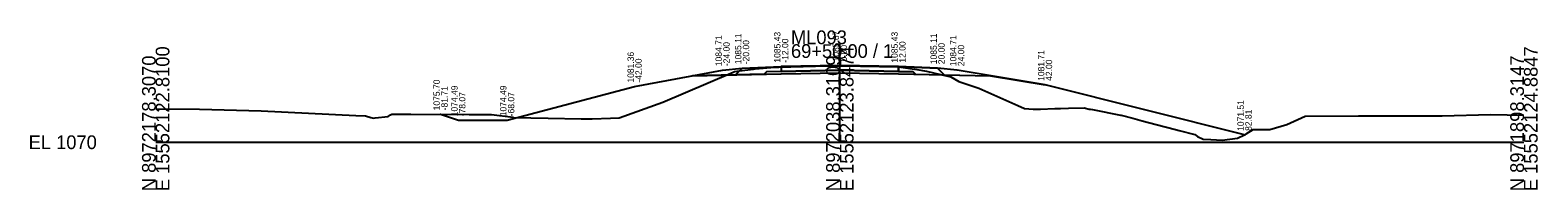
# Model space of a CAD drawing. Extents: x -26 to 14283, y -10 to 28.
# Drawn here: x 5974.3 to 6282.8, y -9.7 to 22.8 of the extents above; entities that cross this region are included whole.
import ezdxf

# ---------------------------------------------------------------- set-up
doc = ezdxf.new("R2010")
doc.units = 0
for name, color, linetype in [('Default', 7, 'Continuous'), ('dsn3DCenterLine', 7, 'Continuous'), ('dsn3DDitchBack', 7, 'Continuous'), ('dsn3DDitchFront', 7, 'Continuous'), ('dsn3DForeSlopeBarnRoofPoint', 7, 'Continuous'), ('dsn3DForeSlopeBreakLine', 7, 'Continuous'), ('dsn3DGroundLineIntercept', 7, 'Continuous'), ('dsn3DPavementTop', 7, 'Continuous'), ('dsn3DShoulderTop', 7, 'Continuous'), ('dsn3DSubgradeBreakLine', 7, 'Continuous'), ('dsn3DSubgradeHingePoint', 7, 'Continuous'), ('dsnGeopakCellCrossSection', 7, 'Continuous'), ('dsnXSEarthwork', 7, 'Continuous'), ('dsnXsExistingGround', 7, 'Continuous'), ('dsnXsPCCPavement', 7, 'Continuous'), ('dsnXsShldrEarthFill', 7, 'Continuous'), ('dsnXsShldrGranular', 7, 'Continuous'), ('dsnXsSideSlopes', 7, 'Continuous'), ('dsnXsSubbase', 7, 'Continuous'), ('dsnXsTextOffsetElevFinGrd', 7, 'Continuous')]:
    doc.layers.add(name, color=color, linetype=linetype)

msp = doc.modelspace()

# ---------------------------------------------------------------- linework, layer by layer
at = {"layer": 'Default'}
for points in [[(6120, 15.11), (6140, 15.67), (6152, 15.43), (6160, 15.11)], [(6109.87, 13.57), (6109.87, 13.57), (6128, 13.93), (6140, 14.17), (6152, 13.93), (6170.84, 13.57), (6182, 11.71)]]:
    msp.add_lwpolyline(points, dxfattribs=at)
at = {"layer": 'dsnGeopakCellCrossSection'}
for p, q in [((6140, 0), (6140, 20)), ((6000, 0), (6140, 0)), ((6140, 0), (6280, 0))]:
    msp.add_line(p, q, dxfattribs=at)
at = {"layer": 'dsnXSEarthwork'}
msp.add_lwpolyline([(6120, 15.11), (6128, 15.43), (6140, 15.67), (6152, 15.43), (6160, 15.11)], dxfattribs=at)
at = {"layer": 'dsnXsExistingGround'}
msp.add_lwpolyline([(6000, 6.84), (6008.93, 6.76), (6021.61, 6.4), (6040.95, 5.47), (6042.9, 5.36), (6044.01, 5.03), (6044.29, 4.95), (6044.54, 4.91), (6044.56, 4.92), (6044.9, 4.95), (6047.56, 5.22), (6048.07, 5.56), (6048.33, 5.7), (6052.19, 5.73), (6064.17, 5.68), (6067.42, 5.68), (6068.74, 5.66), (6073.12, 5.08), (6073.19, 5.07), (6080.33, 4.93), (6087.08, 4.74), (6088.04, 4.77), (6089.33, 4.8), (6093.09, 4.91), (6094.83, 4.95), (6103.75, 8.17), (6117.68, 14.12), (6118.15, 14.32), (6118.37, 14.39), (6118.38, 14.41), (6118.41, 14.44), (6119.4, 14.56), (6122.34, 14.93), (6122.66, 14.97), (6127.53, 15.39), (6130.14, 15.43), (6139.96, 15.59), (6144.23, 15.51), (6152.02, 15.36), (6155.75, 14.83), (6157.76, 14.5), (6160.57, 13.79), (6162.74, 13.33), (6164.35, 12.36), (6168.47, 11), (6174.6, 8.29), (6176.42, 7.46), (6177.8, 6.86), (6179.56, 6.72), (6181.07, 6.76), (6184.01, 6.85), (6185.15, 6.9), (6186.8, 6.95), (6189.99, 7), (6190.99, 6.75), (6191.3, 6.73), (6191.68, 6.67), (6191.72, 6.66), (6197.46, 5.54), (6197.59, 5.51), (6199.94, 4.9), (6201.88, 4.38), (6204.74, 3.62), (6204.76, 3.61), (6208.67, 2.6), (6209.46, 2.38), (6212.64, 1.58), (6213.16, 1.17), (6214.33, 0.61), (6215.95, 0.53), (6218.26, 0.42), (6219.83, 0.63), (6221.4, 0.85), (6222.78, 1.49), (6223.02, 1.6), (6223.16, 1.71), (6224.58, 2.63), (6225.36, 2.62), (6227.99, 2.62), (6231.5, 3.59), (6235.24, 5.33), (6246.13, 5.41), (6263.28, 5.41), (6273.16, 5.68), (6280, 5.52)], dxfattribs=at)
at = {"layer": 'dsnXsPCCPavement'}
msp.add_lwpolyline([(6128, 15.43), (6128, 15.43), (6128, 14.43), (6128, 14.43), (6128, 14.43), (6140, 14.67), (6152, 14.43), (6152, 14.43), (6152, 14.43), (6152, 15.43), (6152, 15.43), (6140, 15.67), (6128, 15.43)], dxfattribs=at)
at = {"layer": 'dsnXsShldrEarthFill'}
for points in [[(6118.63, 13.74), (6109.87, 13.57)], [(6161.36, 13.75), (6170.84, 13.57)]]:
    msp.add_lwpolyline(points, dxfattribs=at)
at = {"layer": 'dsnXsShldrGranular'}
for points in [[(6120, 15.11), (6128, 15.43), (6128, 14.43), (6128, 14.43), (6125, 14.37), (6125, 14.37), (6124.49, 13.86), (6124.49, 13.86), (6124.49, 13.86), (6118.63, 13.74), (6118.63, 13.74), (6120, 15.11), (6120, 15.11)], [(6160, 15.11), (6152, 15.43), (6152, 14.43), (6152, 14.43), (6155, 14.37), (6155, 14.37), (6155.51, 13.86), (6155.51, 13.86), (6161.36, 13.75), (6161.36, 13.75), (6161.36, 13.75), (6160, 15.11), (6160, 15.11)]]:
    msp.add_lwpolyline(points, dxfattribs=at)
at = {"layer": 'dsnXsSideSlopes'}
for points in [[(6058.29, 5.7), (6058.29, 5.7), (6061.93, 4.49), (6061.93, 4.49), (6071.93, 4.49), (6071.93, 4.49), (6098, 11.36), (6116, 14.71), (6116, 14.71), (6116, 14.71), (6120, 15.11)], [(6222.81, 1.51), (6182, 11.71), (6182, 11.71), (6182, 11.71), (6164, 14.71), (6164, 14.71), (6160, 15.11)]]:
    msp.add_lwpolyline(points, dxfattribs=at)
at = {"layer": 'dsnXsSubbase'}
msp.add_lwpolyline([(6124.49, 13.86), (6124.49, 13.86), (6128, 13.93), (6128, 13.93), (6128, 13.93), (6140, 14.17), (6152, 13.93), (6152, 13.93), (6155.51, 13.86), (6155.51, 13.86), (6155.51, 13.86), (6155, 14.37), (6155, 14.37), (6152, 14.43), (6152, 14.43), (6140, 14.67), (6128, 14.43), (6128, 14.43), (6125, 14.37), (6125, 14.37), (6124.49, 13.86)], dxfattribs=at)

# ---------------------------------------------------------------- texts
msp.add_text('-', height=0.0001).set_placement((6000, 0))
at = {"layer": 'dsn3DCenterLine'}
msp.add_text('X', height=0.00781, dxfattribs=at).set_placement((6140, 15.66))
at = {"layer": 'dsn3DDitchBack'}
msp.add_text('X', height=0.00781, dxfattribs=at).set_placement((6061.93, 4.49))
at = {"layer": 'dsn3DDitchFront'}
msp.add_text('X', height=0.00781, dxfattribs=at).set_placement((6071.93, 4.49))
at = {"layer": 'dsn3DForeSlopeBarnRoofPoint'}
for p in [(6098, 11.36), (6182, 11.7)]:
    msp.add_text('X', height=0.00781, dxfattribs=at).set_placement(p)
at = {"layer": 'dsn3DForeSlopeBreakLine'}
for p in [(6116, 14.7), (6164, 14.7)]:
    msp.add_text('X', height=0.00781, dxfattribs=at).set_placement(p)
at = {"layer": 'dsn3DGroundLineIntercept'}
for p in [(6058.28, 5.7), (6222.81, 1.5)]:
    msp.add_text('X', height=0.00781, dxfattribs=at).set_placement(p)
at = {"layer": 'dsn3DPavementTop'}
for p in [(6128, 15.42), (6152, 15.42)]:
    msp.add_text('X', height=0.00781, dxfattribs=at).set_placement(p)
at = {"layer": 'dsn3DShoulderTop'}
for p in [(6120, 15.1), (6160, 15.1)]:
    msp.add_text('X', height=0.00781, dxfattribs=at).set_placement(p)
at = {"layer": 'dsn3DSubgradeBreakLine'}
for p in [(6128, 13.92), (6140, 14.16), (6152, 13.92)]:
    msp.add_text('X', height=0.00781, dxfattribs=at).set_placement(p)
at = {"layer": 'dsn3DSubgradeHingePoint'}
for p in [(6109.87, 13.56), (6170.83, 13.56)]:
    msp.add_text('X', height=0.00781, dxfattribs=at).set_placement(p)
at = {"layer": 'dsnGeopakCellCrossSection'}
for s, p in [('ML093', (6130, 20)), ('69+50.00 / 1', (6130, 17.2)), ('EL 1070', (5974, -1.4))]:
    msp.add_text(s, height=2.8, dxfattribs=at).set_placement(p)
for s, p in [('E 15552122.8100', (6002.8, -10)), ('E 15552123.8474', (6142.8, -10)), ('E 15552124.8847', (6282.8, -10)), ('N 8972178.3070', (6000, -10)), ('N 8972038.3109', (6140, -10)), ('N 8971898.3147', (6280, -10))]:
    msp.add_text(s, height=2.8, rotation=90, dxfattribs=at).set_placement(p)
at = {"layer": 'dsnXsTextOffsetElevFinGrd'}
for s, p in [('1084.71', (6115.85, 15.51)), ('1085.11', (6119.85, 15.91)), ('1085.43', (6127.85, 16.23)), ('1085.43', (6127.85, 16.23)), ('1085.67', (6139.85, 16.47)), ('1085.43', (6151.85, 16.23)), ('1085.11', (6159.85, 15.91)), ('1084.71', (6163.85, 15.51)), ('-24.00', (6117.45, 15.51)), ('-20.00', (6121.45, 15.91)), ('-12.00', (6129.45, 16.23)), ('-12.00', (6129.45, 16.23)), ('0.00', (6141.45, 16.47)), ('12.00', (6153.45, 16.23)), ('20.00', (6161.45, 15.91)), ('24.00', (6165.45, 15.51)), ('1081.71', (6181.85, 12.51)), ('1081.36', (6097.85, 12.16)), ('-42.00', (6099.45, 12.16)), ('42.00', (6183.45, 12.51)), ('1075.70', (6058.14, 6.5)), ('-81.71', (6059.74, 6.5)), ('1074.49', (6061.78, 5.29)), ('-78.07', (6063.38, 5.29)), ('1074.49', (6071.78, 5.29)), ('1074.49', (6071.78, 5.29)), ('-68.07', (6073.38, 5.29)), ('-68.07', (6073.38, 5.29)), ('1071.51', (6222.66, 2.31)), ('82.81', (6224.26, 2.31))]:
    msp.add_text(s, height=1.3, rotation=90, dxfattribs=at).set_placement(p)

doc.saveas('drawing.dxf')
